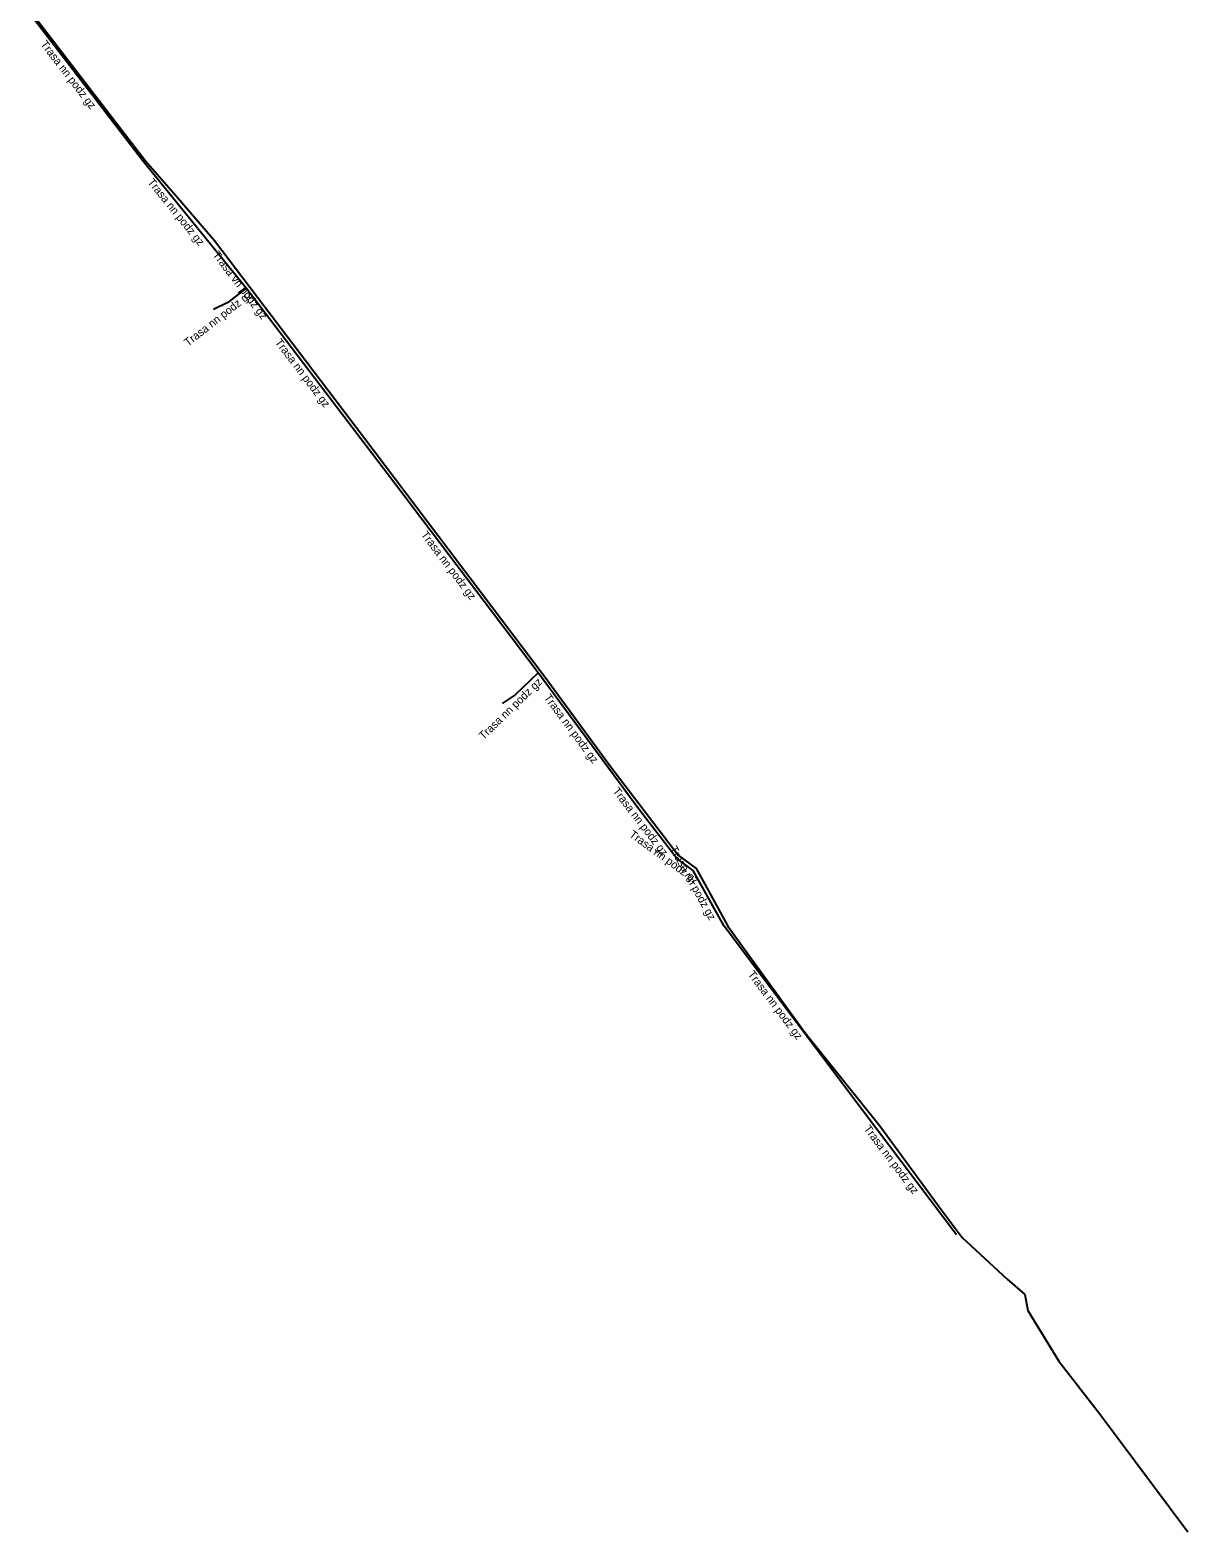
# Model space of a CAD drawing. Extents: x -671755 to -671440, y -1012943 to -1012521.
# Drawn here: x -671692.5 to -671620.2, y -1012921.4 to -1012827.6 of the extents above; entities that cross this region are included whole.
import ezdxf

# ---------------------------------------------------------------- set-up
doc = ezdxf.new("R2010")
doc.units = 0
for name, color, linetype in [('Popiskový text - Ostatní atributy Trasy', 7, 'Continuous'), ('Spojnice NN', 7, 'Continuous'), ('Spojnice VN', 7, 'Continuous')]:
    doc.layers.add(name, color=color, linetype=linetype)

msp = doc.modelspace()

# ---------------------------------------------------------------- linework, layer by layer
at = {"layer": 'Spojnice NN'}
for points in [[(-671685.51, -1012835.7), (-671692.54, -1012826.57)], [(-671679.04, -1012843.67), (-671685.51, -1012835.7)], [(-671679.04, -1012843.67), (-671680.19, -1012844.57), (-671681.082, -1012845.009)], [(-671669.76, -1012855.88), (-671679.04, -1012843.67)], [(-671660.81, -1012867.71), (-671669.76, -1012855.88)], [(-671660.81, -1012867.71), (-671662.238, -1012869.091), (-671663.067, -1012869.624)], [(-671654.45, -1012876.3), (-671660.81, -1012867.71)], [(-671652.15, -1012879.3), (-671654.45, -1012876.3)], [(-671651.12, -1012880.05), (-671652.15, -1012879.3)], [(-671649.19, -1012883.53), (-671651.12, -1012880.05)], [(-671640.58, -1012895.01), (-671649.19, -1012883.53)], [(-671634.69, -1012902.82), (-671640.58, -1012895.01)]]:
    msp.add_lwpolyline(points, dxfattribs=at)
at = {"layer": 'Spojnice VN'}
msp.add_lwpolyline([(-671692.48, -1012826.43), (-671685.34, -1012835.73), (-671683.44, -1012837.88), (-671681.03, -1012840.7), (-671671.71, -1012852.97), (-671660.43, -1012867.9), (-671656.33, -1012873.5), (-671652.05, -1012879.12), (-671650.94, -1012879.93), (-671650.4, -1012880.91), (-671648.96, -1012883.53), (-671644.13, -1012890.2), (-671639.48, -1012896), (-671635.64, -1012901.23), (-671634.32, -1012902.98), (-671631.52, -1012905.58), (-671630.42, -1012906.55), (-671630.23, -1012907.55), (-671628.29, -1012910.71), (-671625.76, -1012913.97), (-671620.23, -1012921.38)], dxfattribs=at)

# ---------------------------------------------------------------- texts
at = {"layer": 'Popiskový text - Ostatní atributy Trasy'}
for s, rotation, p in [('Trasa nn podz gz', 307.59588, (-671691.916, -1012828.446)), ('Trasa nn podz gz', 309.06949, (-671685.234, -1012837.072)), ('Trasa vn podz gz', 307.21944, (-671681.163, -1012841.6)), ('Trasa nn podz gz', 38.04704, (-671682.672, -1012847.338)), ('Trasa nn podz gz', 307.23602, (-671677.273, -1012847.068)), ('Trasa nn podz gz', 307.10937, (-671668.153, -1012859.082)), ('Trasa nn podz gz', 44.04142, (-671664.225, -1012871.918)), ('Trasa nn podz gz', 306.51609, (-671660.469, -1012869.262)), ('Trasa nn podz gz', 307.47618, (-671656.184, -1012875.105)), ('Trasa nn podz gz', 323.93956, (-671655.165, -1012877.908)), ('Trasa nn podz gz', 299.01265, (-671652.612, -1012878.7)), ('Trasa nn podz gz', 306.8699, (-671647.741, -1012886.545)), ('Trasa nn podz gz', 307.02219, (-671640.498, -1012896.198))]:
    msp.add_text(s, height=0.5, rotation=rotation, dxfattribs=at).set_placement(p)

doc.saveas('drawing.dxf')
